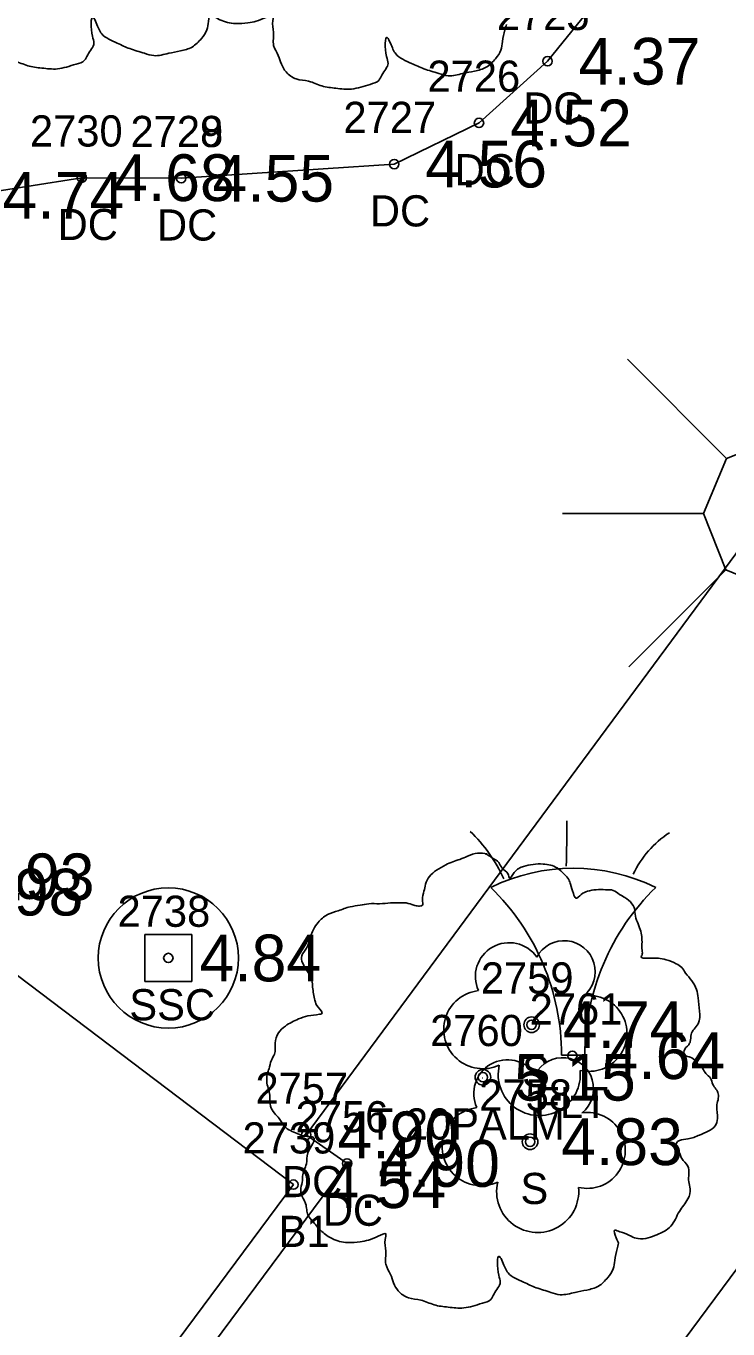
# Model space of a CAD drawing. Extents: x 2608598 to 2610682, y 641451 to 643526.
# Drawn here: x 2610136.19 to 2610158.72, y 641996.54 to 642038.34 of the extents above; entities that cross this region are included whole.
import ezdxf

# ---------------------------------------------------------------- set-up
doc = ezdxf.new("R2010")
doc.units = 0
for name, color, linetype in [('RD_EX_Bldg', 7, 'Continuous'), ('RD_EX_Bldg_txCode', 7, 'Continuous'), ('RD_EX_BldgApp', 7, 'Continuous'), ('RD_EX_BldgApp_txCode', 7, 'Continuous'), ('RD_EX_Conc', 7, 'Continuous'), ('RD_EX_Conc_txCode', 7, 'Continuous'), ('RD_EX_TX_Bldg_ELEV', 7, 'Continuous'), ('RD_EX_TX_BldgApp_ELEV', 7, 'Continuous'), ('RD_EX_TX_Conc_ELEV', 7, 'Continuous'), ('RD_EX_TX_UT_ELEV', 7, 'Continuous'), ('RD_EX_TX_VEG_ELEV', 7, 'Continuous'), ('RD_EX_UT', 7, 'Continuous'), ('RD_EX_UT_txCode', 7, 'Continuous'), ('RD_EX_VEG', 7, 'Continuous'), ('RD_EX_VEG_txCode', 7, 'Continuous'), ('RD_SMD_Locator', 7, 'Continuous')]:
    doc.layers.add(name, color=color, linetype=linetype)

msp = doc.modelspace()

# ---------------------------------------------------------------- linework, layer by layer
at = {"layer": 'RD_EX_Bldg'}
for points in [[(2610074.75, 641955.019), (2610121.892, 642018.487), (2610144.774, 642001.166), (2610097.632, 641937.698), (2610074.75, 641955.019)], [(2610117.49, 641942.534), (2610163.776, 642004.891), (2610174.799, 641996.666), (2610165.228, 641983.772), (2610177.626, 641974.569), (2610167.76, 641961.766), (2610177.196, 641954.91), (2610150.309, 641918.688), (2610117.49, 641942.534)]]:
    msp.add_lwpolyline(points, dxfattribs=at)
at = {"layer": 'RD_EX_BldgApp'}
for p, q in [((2610158.677, 642024.47), (2610155.494, 642027.653)), ((2610157.934, 642022.706), (2610153.411, 642022.706)), ((2610158.652, 642020.894), (2610155.535, 642017.777)), ((2610153.38, 642005.322), (2610154.13, 642005.322))]:
    msp.add_line(p, q, dxfattribs=at)
msp.add_lwpolyline([(2610158.677, 642024.47), (2610160.464, 642025.168), (2610162.215, 642024.399), (2610162.939, 642022.624), (2610162.161, 642020.87), (2610160.423, 642020.163), (2610158.652, 642020.894), (2610157.934, 642022.706)], close=True, dxfattribs=at)
for centre, radius, start, end in [((2610147.063, 642008.964), 4.895, 24.3279, 46.2665), ((2610115.674, 642012.66), 37.876, 358.0671, 0.2715), ((2610158.643, 642009.715), 3.283, 123.2906, 154.4886), ((2610153.755, 642005.322), 5.997, 63.7794, 116.2206), ((2610145.88, 642005.322), 7.5, 0, 45.8366), ((2610161.63, 642005.322), 7.5, 134.1634, 180)]:
    msp.add_arc(centre, radius, start, end, dxfattribs=at)
at = {"layer": 'RD_EX_Conc'}
for points in [[(2610160.612, 642047.272), (2610156.554, 642041.695), (2610152.931, 642037.213), (2610150.731, 642035.233), (2610148.01, 642033.912), (2610141.177, 642033.459), (2610141.177, 642033.459), (2610137.988, 642033.476), (2610134.44, 642032.913), (2610131.048, 642029.279), (2610128.16, 642026.009), (2610122.885, 642018.814), (2610128.446, 642014.737), (2610133.488, 642011.041), (2610133.129, 642010.552)], [(2610097.632, 641937.698), (2610098.418, 641937.114), (2610146.498, 642001.846), (2610145.188, 642002.764), (2610160.492, 642023.462), (2610172.047, 642039.304)]]:
    msp.add_lwpolyline(points, dxfattribs=at)
at = {"layer": 'RD_EX_UT'}
for p, q in [((2610141.511, 642009.189), (2610140.011, 642009.189)), ((2610140.011, 642009.189), (2610140.011, 642007.689)), ((2610141.511, 642007.688), (2610141.511, 642009.189)), ((2610140.011, 642007.689), (2610141.511, 642007.688))]:
    msp.add_line(p, q, dxfattribs=at)
msp.add_circle((2610140.761, 642008.439), 2.25, dxfattribs=at)
at = {"layer": 'RD_EX_VEG'}
for centre, radius in [((2610152.42, 642006.298), 0.25), ((2610150.857, 642004.612), 0.25), ((2610150.845, 642004.593), 0.0001), ((2610152.369, 642002.543), 0.25)]:
    msp.add_circle(centre, radius, dxfattribs=at)
for centre, radius, start, end in [((2610151.699, 642007.845), 1.084, 34.9763, 204.756), ((2610153.465, 642008), 0.995, 308.7626, 152.0467), ((2610150.856, 642006.142), 1.257, 96.4518, 294.734), ((2610154.259, 642006.018), 1.218, 256.5667, 98.1046), ((2610151.647, 642004.09), 1.084, 34.9763, 204.756), ((2610152.665, 642004.701), 1.318, 166.8827, 5.7589), ((2610153.414, 642004.245), 0.995, 308.7626, 152.0467), ((2610150.805, 642002.388), 1.257, 96.4518, 294.734), ((2610154.208, 642002.264), 1.218, 256.5667, 98.1046), ((2610152.614, 642000.947), 1.318, 166.8827, 5.7589)]:
    msp.add_arc(centre, radius, start, end, dxfattribs=at)
for points in [[(2610137.949, 642051.536), (2610137.649, 642051.561), (2610137.324, 642051.461), (2610137.074, 642051.361), (2610136.849, 642051.286), (2610136.624, 642051.186), (2610136.324, 642051.011), (2610136.1, 642050.811), (2610135.975, 642050.561), (2610135.925, 642050.336), (2610135.875, 642050.062), (2610135.875, 642049.887), (2610135.75, 642049.862), (2610135.6, 642049.887), (2610135.35, 642049.962), (2610135.1, 642049.962), (2610134.85, 642049.962), (2610134.5, 642049.937), (2610134.15, 642049.937), (2610133.876, 642049.887), (2610133.551, 642049.837), (2610133.176, 642049.712), (2610132.826, 642049.587), (2610132.526, 642049.337), (2610132.276, 642048.862), (2610132.151, 642048.512), (2610132.001, 642048.262), (2610132.151, 642047.813), (2610132.326, 642047.463), (2610132.351, 642047.263), (2610132.426, 642046.838), (2610132.526, 642046.613), (2610132.651, 642046.413), (2610132.576, 642046.388), (2610132.201, 642046.338), (2610131.901, 642046.238), (2610131.477, 642046.013), (2610131.252, 642045.788), (2610131.152, 642045.464), (2610131.127, 642045.114), (2610131.027, 642044.914), (2610130.952, 642044.639), (2610130.927, 642044.564), (2610130.877, 642044.239), (2610130.977, 642043.789), (2610131.002, 642043.439), (2610131.127, 642043.215), (2610131.277, 642043.04), (2610131.452, 642042.79), (2610131.851, 642042.565), (2610132.176, 642042.465), (2610132.376, 642042.44), (2610132.201, 642041.94), (2610132.151, 642041.59), (2610132.026, 642041.19), (2610132.026, 642041.116), (2610131.976, 642040.641), (2610132.126, 642040.316), (2610132.201, 642039.941), (2610132.376, 642039.716), (2610132.651, 642039.416), (2610132.976, 642039.191), (2610133.476, 642039.066), (2610133.876, 642039.091), (2610134.45, 642039.266), (2610134.7, 642039.341), (2610134.675, 642039.166), (2610134.7, 642038.791), (2610134.7, 642038.367), (2610134.85, 642038.042), (2610134.95, 642037.767), (2610135.1, 642037.517), (2610135.425, 642037.292), (2610135.825, 642037.217), (2610136.249, 642037.067), (2610136.699, 642036.992), (2610137.199, 642036.967), (2610137.799, 642037.117), (2610138.074, 642037.242), (2610138.174, 642037.417), (2610138.374, 642037.792), (2610138.324, 642038.017), (2610138.349, 642038.617), (2610138.448, 642038.442), (2610138.623, 642038.092), (2610139.123, 642037.792), (2610139.523, 642037.617), (2610139.998, 642037.467), (2610140.298, 642037.392), (2610140.772, 642037.467), (2610141.147, 642037.542), (2610141.522, 642037.667), (2610141.822, 642037.942), (2610141.997, 642038.217), (2610142.047, 642038.492), (2610142.122, 642038.866), (2610142.172, 642039.041)], [(2610147.388, 642050.889), (2610147.088, 642050.914), (2610146.764, 642050.814), (2610146.514, 642050.715), (2610146.289, 642050.64), (2610146.064, 642050.54), (2610145.764, 642050.365), (2610145.539, 642050.165), (2610145.414, 642049.915), (2610145.364, 642049.69), (2610145.314, 642049.415), (2610145.314, 642049.24), (2610145.189, 642049.215), (2610145.039, 642049.24), (2610144.789, 642049.315), (2610144.539, 642049.315), (2610144.29, 642049.315), (2610143.94, 642049.29), (2610143.59, 642049.29), (2610143.315, 642049.24), (2610142.99, 642049.19), (2610142.615, 642049.065), (2610142.265, 642048.94), (2610141.966, 642048.69), (2610141.716, 642048.216), (2610141.591, 642047.866), (2610141.441, 642047.616), (2610141.591, 642047.166), (2610141.766, 642046.816), (2610141.791, 642046.616), (2610141.866, 642046.192), (2610141.966, 642045.967), (2610142.091, 642045.767), (2610142.016, 642045.742), (2610141.641, 642045.692), (2610141.341, 642045.592), (2610140.916, 642045.367), (2610140.691, 642045.142), (2610140.591, 642044.817), (2610140.566, 642044.467), (2610140.466, 642044.267), (2610140.391, 642043.992), (2610140.366, 642043.917), (2610140.316, 642043.593), (2610140.416, 642043.143), (2610140.441, 642042.793), (2610140.566, 642042.568), (2610140.716, 642042.393), (2610140.891, 642042.143), (2610141.291, 642041.918), (2610141.616, 642041.818), (2610141.816, 642041.793), (2610141.641, 642041.294), (2610141.591, 642040.944), (2610141.466, 642040.544), (2610141.466, 642040.469), (2610141.416, 642039.994), (2610141.566, 642039.669), (2610141.641, 642039.295), (2610141.816, 642039.07), (2610142.091, 642038.77), (2610142.415, 642038.545), (2610142.915, 642038.42), (2610143.315, 642038.445), (2610143.89, 642038.62), (2610144.14, 642038.695), (2610144.115, 642038.52), (2610144.14, 642038.145), (2610144.14, 642037.72), (2610144.29, 642037.395), (2610144.39, 642037.12), (2610144.539, 642036.871), (2610144.864, 642036.646), (2610145.264, 642036.571), (2610145.689, 642036.421), (2610146.139, 642036.346), (2610146.639, 642036.321), (2610147.238, 642036.471), (2610147.513, 642036.596), (2610147.613, 642036.771), (2610147.813, 642037.145), (2610147.763, 642037.37), (2610147.788, 642037.97), (2610147.888, 642037.795), (2610148.063, 642037.445), (2610148.563, 642037.145), (2610148.963, 642036.971), (2610149.437, 642036.821), (2610149.737, 642036.746), (2610150.212, 642036.821), (2610150.587, 642036.896), (2610150.962, 642037.021), (2610151.262, 642037.295), (2610151.436, 642037.57), (2610151.486, 642037.845), (2610151.561, 642038.22), (2610151.611, 642038.395)], [(2610150.989, 642011.779), (2610150.689, 642011.804), (2610150.365, 642011.704), (2610150.115, 642011.604), (2610149.89, 642011.529), (2610149.665, 642011.429), (2610149.365, 642011.254), (2610149.14, 642011.054), (2610149.015, 642010.804), (2610148.965, 642010.58), (2610148.915, 642010.305), (2610148.915, 642010.13), (2610148.79, 642010.105), (2610148.64, 642010.13), (2610148.39, 642010.205), (2610148.14, 642010.205), (2610147.891, 642010.205), (2610147.541, 642010.18), (2610147.191, 642010.18), (2610146.916, 642010.13), (2610146.591, 642010.08), (2610146.216, 642009.955), (2610145.866, 642009.83), (2610145.567, 642009.58), (2610145.317, 642009.105), (2610145.192, 642008.755), (2610145.042, 642008.505), (2610145.192, 642008.056), (2610145.367, 642007.706), (2610145.392, 642007.506), (2610145.467, 642007.081), (2610145.567, 642006.856), (2610145.692, 642006.656), (2610145.617, 642006.631), (2610145.242, 642006.581), (2610144.942, 642006.481), (2610144.517, 642006.256), (2610144.292, 642006.032), (2610144.192, 642005.707), (2610144.167, 642005.357), (2610144.067, 642005.157), (2610143.992, 642004.882), (2610143.967, 642004.807), (2610143.917, 642004.482), (2610144.017, 642004.032), (2610144.042, 642003.683), (2610144.167, 642003.458), (2610144.317, 642003.283), (2610144.492, 642003.033), (2610144.892, 642002.808), (2610145.217, 642002.708), (2610145.417, 642002.683), (2610145.242, 642002.183), (2610145.192, 642001.833), (2610145.067, 642001.434), (2610145.067, 642001.359), (2610145.017, 642000.884), (2610145.167, 642000.559), (2610145.242, 642000.184), (2610145.417, 641999.959), (2610145.692, 641999.659), (2610146.016, 641999.434), (2610146.516, 641999.309), (2610146.916, 641999.334), (2610147.491, 641999.509), (2610147.741, 641999.584), (2610147.716, 641999.409), (2610147.741, 641999.035), (2610147.741, 641998.61), (2610147.891, 641998.285), (2610147.991, 641998.01), (2610148.14, 641997.76), (2610148.465, 641997.535), (2610148.865, 641997.46), (2610149.29, 641997.31), (2610149.74, 641997.235), (2610150.24, 641997.21), (2610150.839, 641997.36), (2610151.114, 641997.485), (2610151.214, 641997.66), (2610151.414, 641998.035), (2610151.364, 641998.26), (2610151.389, 641998.86), (2610151.489, 641998.685), (2610151.664, 641998.335), (2610152.164, 641998.035), (2610152.564, 641997.86), (2610153.038, 641997.71), (2610153.338, 641997.635), (2610153.813, 641997.71), (2610154.188, 641997.785), (2610154.563, 641997.91), (2610154.863, 641998.185), (2610155.037, 641998.46), (2610155.087, 641998.735), (2610155.162, 641999.11), (2610155.212, 641999.284)], [(2610155.212, 641999.284), (2610155.137, 641999.459), (2610155.087, 641999.709), (2610155.162, 641999.684), (2610155.337, 641999.634), (2610155.612, 641999.509), (2610155.837, 641999.434), (2610156.162, 641999.459), (2610156.437, 641999.559), (2610156.887, 641999.834), (2610157.162, 642000.309), (2610157.436, 642000.709), (2610157.511, 642001.034), (2610157.461, 642001.259), (2610157.436, 642001.758), (2610157.236, 642002.008), (2610157.186, 642002.133), (2610157.087, 642002.533), (2610157.162, 642002.583), (2610157.436, 642002.633), (2610157.811, 642002.758), (2610158.086, 642002.883), (2610158.311, 642003.058), (2610158.386, 642003.283), (2610158.361, 642003.683), (2610158.411, 642004.082), (2610158.336, 642004.232), (2610158.236, 642004.382), (2610158.161, 642004.582), (2610158.011, 642004.732), (2610157.911, 642004.882), (2610157.811, 642004.982), (2610157.686, 642005.132), (2610157.511, 642005.257), (2610157.361, 642005.307), (2610157.311, 642005.457), (2610157.461, 642005.657), (2610157.511, 642005.757), (2610157.536, 642005.982), (2610157.761, 642006.331), (2610157.811, 642006.731), (2610157.761, 642007.156), (2610157.711, 642007.431), (2610157.561, 642007.706), (2610157.361, 642007.956), (2610157.236, 642008.131), (2610157.062, 642008.256), (2610156.737, 642008.381), (2610156.487, 642008.43), (2610156.137, 642008.43), (2610155.937, 642008.48), (2610155.962, 642008.53), (2610155.962, 642008.68), (2610155.962, 642008.955), (2610155.887, 642009.405), (2610155.737, 642009.905), (2610155.737, 642009.93), (2610155.637, 642010.18), (2610155.412, 642010.38), (2610155.237, 642010.48), (2610155.037, 642010.605), (2610154.788, 642010.63), (2610154.488, 642010.63), (2610154.213, 642010.58), (2610154.013, 642010.48), (2610153.838, 642010.355), (2610153.763, 642010.505), (2610153.663, 642010.804), (2610153.613, 642010.954), (2610153.463, 642011.129), (2610153.238, 642011.329), (2610152.788, 642011.454), (2610152.164, 642011.379), (2610151.864, 642011.179), (2610151.714, 642011.004), (2610151.664, 642011.129), (2610151.464, 642011.329), (2610151.364, 642011.504), (2610151.189, 642011.629), (2610151.039, 642011.729), (2610150.939, 642011.779)]]:
    msp.add_spline(points, degree=3, dxfattribs=at)
at = {"layer": 'RD_SMD_Locator'}
for centre in [(2610152.931, 642037.213), (2610150.731, 642035.233), (2610148.01, 642033.912), (2610137.988, 642033.476), (2610141.177, 642033.459), (2610141.177, 642033.459), (2610140.761, 642008.439), (2610152.42, 642006.298), (2610153.727, 642005.304), (2610150.857, 642004.612), (2610145.188, 642002.764), (2610152.369, 642002.543), (2610146.498, 642001.846), (2610144.774, 642001.166)]:
    msp.add_circle(centre, 0.15, dxfattribs=at)

# ---------------------------------------------------------------- texts
at = {"layer": 'RD_EX_Bldg_txCode'}
for s, p in [('2739', (2610143.144, 642002.166)), ('B1', (2610144.301, 641999.166))]:
    msp.add_text(s, height=1, dxfattribs=at).set_placement(p)
at = {"layer": 'RD_EX_BldgApp_txCode'}
for s, p in [('2761', (2610152.357, 642006.304)), ('FLT', (2610152.507, 642003.304))]:
    msp.add_text(s, height=1, dxfattribs=at).set_placement(p)
at = {"layer": 'RD_EX_Conc_txCode'}
for s, p in [('2725', (2610151.301, 642038.213)), ('2726', (2610149.077, 642036.233)), ('2727', (2610146.38, 642034.912)), ('DC', (2610152.151, 642035.213)), ('2730', (2610136.319, 642034.476)), ('2728', (2610139.547, 642034.459)), ('2729', (2610139.547, 642034.459)), ('DC', (2610149.951, 642033.233)), ('DC', (2610147.23, 642031.912)), ('DC', (2610137.209, 642031.476)), ('DC', (2610140.398, 642031.459)), ('DC', (2610140.398, 642031.459)), ('2757', (2610143.558, 642003.764)), ('2756', (2610144.845, 642002.846)), ('DC', (2610144.408, 642000.764)), ('DC', (2610145.719, 641999.846))]:
    msp.add_text(s, height=1, dxfattribs=at).set_placement(p)
at = {"layer": 'RD_EX_TX_Bldg_ELEV'}
msp.add_text('4.54', height=1.5, dxfattribs=at).set_placement((2610145.774, 642000.416))
at = {"layer": 'RD_EX_TX_BldgApp_ELEV'}
msp.add_text('4.64', height=1.5, dxfattribs=at).set_placement((2610154.727, 642004.554))
at = {"layer": 'RD_EX_TX_Conc_ELEV'}
for s, p in [('4.37', (2610153.931, 642036.463)), ('4.52', (2610151.731, 642034.483)), ('4.56', (2610149.01, 642033.162)), ('4.68', (2610138.988, 642032.726)), ('4.55', (2610142.177, 642032.709)), ('4.55', (2610142.177, 642032.709)), ('4.74', (2610135.44, 642032.163)), ('4.93', (2610134.488, 642010.291)), ('4.98', (2610134.129, 642009.802)), ('4.90', (2610146.188, 642002.014)), ('4.90', (2610147.498, 642001.096))]:
    msp.add_text(s, height=1.5, dxfattribs=at).set_placement(p)
at = {"layer": 'RD_EX_TX_UT_ELEV'}
msp.add_text('4.84', height=1.5, dxfattribs=at).set_placement((2610141.761, 642007.689))
at = {"layer": 'RD_EX_TX_VEG_ELEV'}
for s, p in [('4.74', (2610153.42, 642005.548)), ('5.15', (2610151.857, 642003.862)), ('4.83', (2610153.369, 642001.793))]:
    msp.add_text(s, height=1.5, dxfattribs=at).set_placement(p)
at = {"layer": 'RD_EX_UT_txCode'}
for s, p in [('2738', (2610139.131, 642009.439)), ('SSC', (2610139.509, 642006.439))]:
    msp.add_text(s, height=1, dxfattribs=at).set_placement(p)
at = {"layer": 'RD_EX_VEG_txCode'}
for s, p in [('2759', (2610150.79, 642007.298)), ('2760', (2610149.164, 642005.612)), ('S', (2610152.113, 642004.298)), ('2758', (2610150.739, 642003.543)), ('T 20PALM', (2610147.164, 642002.612)), ('S', (2610152.061, 642000.543))]:
    msp.add_text(s, height=1, dxfattribs=at).set_placement(p)

doc.saveas('drawing.dxf')
